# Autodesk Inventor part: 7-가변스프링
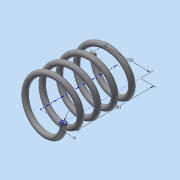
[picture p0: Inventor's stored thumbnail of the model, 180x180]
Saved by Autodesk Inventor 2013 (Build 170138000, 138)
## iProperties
Created: 2015-03
Part Number: 7-가변스프링
Material: 강철, 탄소
Document SubType Name: Modeling
Designer: Administrator
Density: 7.87 g/cm^3
Mass: 48.2733 g
Surface Area: 62.0009 cm^2
Volume: 6.13383 cm^3
Author: Administrator
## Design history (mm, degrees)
sketch "스케치1"
  geometry: L1 (0, 0)-(17.5, 0); L2 (17.5, 0)-(17.5, 43.5); L3 (17.5, 43.5)-(0, 43.5); L4 (0, 43.5)-(0, 0); C1 r 2 at (17.5, 0)
  constraints: 8 end point, 2 parallel, 1 centre point, 1 coincident, 1 horizontal, 1 perpendicular
  dimensions: "d0" = 43.5 distance of L1.end L2.end (derived); "d2" = 35 diameter of L2 L4; "d3" = 4 diameter of C1
feature "코일1" sketch "스케치1" pitch "d4" = 10; turns "d6" = 4.5; dims "d5" = 43.5 (= d0), "d7" = 0, angle "d8" = 90 deg, angle "d9" = 90 deg, "d10" = 0, "d11" = 0
node "작업 평면1"
sketch "스케치2"
  geometry: L1 (-19.5, 0)-(-15.5, 0) reference; 1 further point
  constraints: 1 horizontal alignment
extrude "돌출1" cut sketch "스케치2" stored distance "d13" = 10; taper "d14" = 0 deg
node "작업 평면2"
sketch "스케치3"
  geometry: L1 (-19.5, 0)-(-15.5, 0) reference; 1 further point
  constraints: 1 horizontal alignment
extrude "돌출2" cut sketch "스케치3" stored distance "d16" = 10; taper "d17" = 0 deg
node "솔리드1"
node "절단 모서리 투영1"
node "절단 모서리 투영2"
other parameters: "d12" = 0, "d15" = -43.5 (= -d0)
